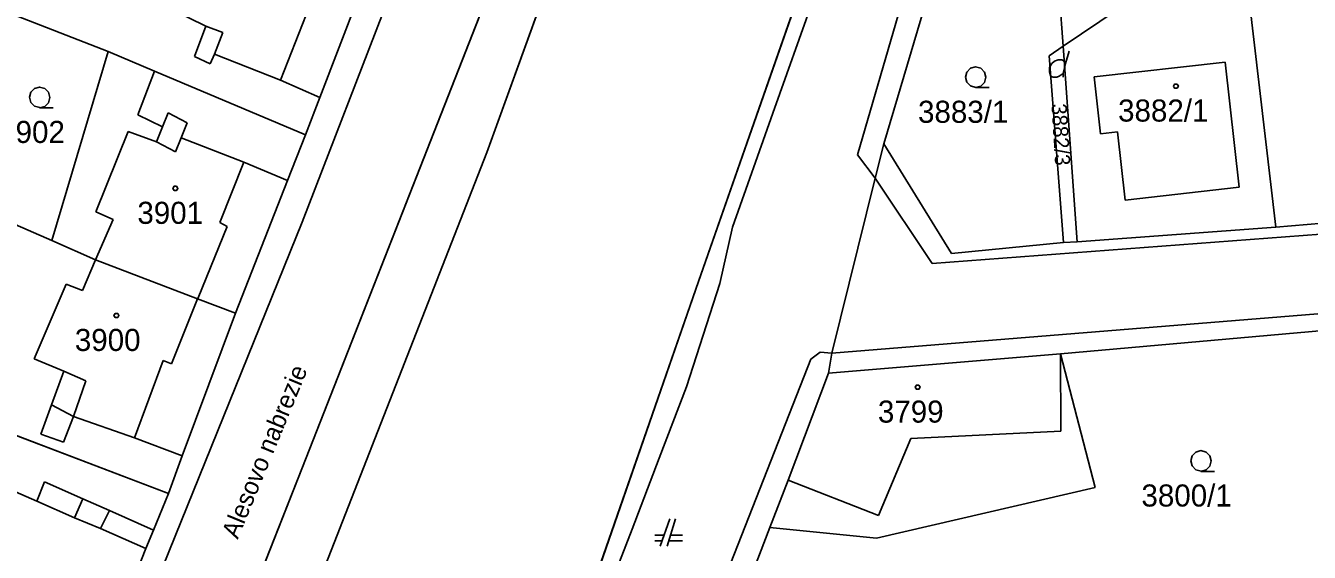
# Model space of a CAD drawing. Extents: x -263587 to -261993, y -1238795 to -1236748.
# Drawn here: x -262910.7 to -262817.7, y -1238176 to -1238137.9 of the extents above; entities that cross this region are included whole.
import ezdxf

# ---------------------------------------------------------------- set-up
doc = ezdxf.new("R2010")
doc.units = 0
for name, color, linetype in [('Vrstva 1', 7, 'Continuous'), ('Vrstva 2', 7, 'Continuous'), ('Vrstva 3', 7, 'Continuous')]:
    doc.layers.add(name, color=color, linetype=linetype)

msp = doc.modelspace()

# ---------------------------------------------------------------- linework, layer by layer
at = {"layer": 'Vrstva 1'}
for p, q in [((-262866.29, -1238107.87), (-262890.35, -1238169.19)), ((-262876.21, -1238114.77), (-262890.62, -1238152.1)), ((-262840.79, -1238114.19), (-262850.4, -1238147.22)), ((-262867.06, -1238118.93), (-262877.26, -1238147.05)), ((-262877.26, -1238147.05), (-262867.06, -1238118.93)), ((-262861.93, -1238156.4), (-262852.81, -1238130.33)), ((-262852.81, -1238130.33), (-262861.93, -1238156.4)), ((-262844.29, -1238132.25), (-262848.49, -1238146.42)), ((-262848.49, -1238146.42), (-262844.29, -1238132.25)), ((-262885.33, -1238132.63), (-262889.36, -1238143.08)), ((-262889.36, -1238143.08), (-262885.33, -1238132.63)), ((-262835.51, -1238139.35), (-262826.23, -1238133.08)), ((-262826.23, -1238133.08), (-262835.51, -1238139.35)), ((-262820.12, -1238152.47), (-262822.35, -1238133.41)), ((-262822.35, -1238133.41), (-262820.12, -1238152.47)), ((-262835.51, -1238139.35), (-262835.88, -1238134.17)), ((-262835.88, -1238134.17), (-262835.51, -1238139.35)), ((-262912.18, -1238136.81), (-262904.69, -1238139.75)), ((-262904.69, -1238139.75), (-262912.18, -1238136.81)), ((-262900.12, -1238136.67), (-262897.61, -1238137.9)), ((-262890.33, -1238137.09), (-262892.19, -1238141.83)), ((-262898.43, -1238140.1), (-262897.61, -1238137.9)), ((-262897.61, -1238137.9), (-262896.38, -1238138.37)), ((-262896.38, -1238138.37), (-262896.97, -1238139.94)), ((-262904.69, -1238139.75), (-262908.77, -1238153.43)), ((-262908.77, -1238153.43), (-262904.69, -1238139.75)), ((-262904.69, -1238139.75), (-262901.32, -1238141.17)), ((-262901.32, -1238141.17), (-262904.69, -1238139.75)), ((-262896.97, -1238139.94), (-262897.29, -1238140.63)), ((-262892.19, -1238141.83), (-262896.97, -1238139.94)), ((-262836.52, -1238140.05), (-262835.51, -1238139.35)), ((-262835.51, -1238139.35), (-262836.52, -1238140.05)), ((-262835.48, -1238153.58), (-262836.52, -1238140.05)), ((-262836.52, -1238140.05), (-262835.48, -1238153.58)), ((-262834.5, -1238153.53), (-262835.51, -1238139.35)), ((-262835.51, -1238139.35), (-262834.5, -1238153.53)), ((-262835.34, -1238140.62), (-262835.07, -1238139.72)), ((-262897.29, -1238140.63), (-262898.43, -1238140.1)), ((-262833.26, -1238141.57), (-262823.79, -1238140.51)), ((-262823.79, -1238140.51), (-262822.77, -1238149.58)), ((-262901.32, -1238141.17), (-262902.54, -1238144.34)), ((-262901.32, -1238141.17), (-262890.39, -1238145.77)), ((-262890.39, -1238145.77), (-262901.32, -1238141.17)), ((-262889.36, -1238143.08), (-262892.19, -1238141.83)), ((-262832.8, -1238145.7), (-262833.26, -1238141.57)), ((-262889.36, -1238143.08), (-262890.39, -1238145.77)), ((-262890.39, -1238145.77), (-262889.36, -1238143.08)), ((-262902.54, -1238144.34), (-262900.74, -1238145.2)), ((-262900.33, -1238144.19), (-262900.74, -1238145.2)), ((-262898.96, -1238144.9), (-262900.33, -1238144.19)), ((-262905.57, -1238151.35), (-262903.22, -1238145.53)), ((-262903.22, -1238145.53), (-262901.17, -1238146.29)), ((-262900.74, -1238145.2), (-262901.17, -1238146.29)), ((-262899.38, -1238146), (-262898.96, -1238144.9)), ((-262831.57, -1238145.57), (-262832.8, -1238145.7)), ((-262831.02, -1238150.51), (-262831.57, -1238145.57)), ((-262901.17, -1238146.29), (-262899.8, -1238147.02)), ((-262899.8, -1238147.02), (-262899.38, -1238146)), ((-262894.86, -1238147.75), (-262899.38, -1238146)), ((-262890.39, -1238145.77), (-262891.69, -1238149.1)), ((-262891.69, -1238149.1), (-262890.39, -1238145.77)), ((-262849.13, -1238148.92), (-262848.49, -1238146.42)), ((-262848.49, -1238146.42), (-262849.13, -1238148.92)), ((-262848.49, -1238146.42), (-262843.6, -1238154.37)), ((-262843.6, -1238154.37), (-262848.49, -1238146.42)), ((-262877.26, -1238147.05), (-262889.19, -1238177.55)), ((-262889.19, -1238177.55), (-262877.26, -1238147.05)), ((-262850.4, -1238147.22), (-262849.13, -1238148.92)), ((-262896.6, -1238152.13), (-262894.86, -1238147.75)), ((-262891.69, -1238149.1), (-262894.86, -1238147.75)), ((-262891.69, -1238149.1), (-262895.45, -1238158.69)), ((-262895.45, -1238158.69), (-262891.69, -1238149.1)), ((-262852.27, -1238161.6), (-262849.13, -1238148.92)), ((-262849.13, -1238148.92), (-262852.27, -1238161.6)), ((-262844.99, -1238155.11), (-262849.13, -1238148.92)), ((-262822.77, -1238149.58), (-262831.02, -1238150.51)), ((-262788.07, -1238150.8), (-262844.99, -1238155.11)), ((-262805.26, -1238151.2), (-262820.12, -1238152.47)), ((-262820.12, -1238152.47), (-262805.26, -1238151.2)), ((-262911.8, -1238152.11), (-262908.77, -1238153.43)), ((-262908.77, -1238153.43), (-262911.8, -1238152.11)), ((-262890.62, -1238152.1), (-262911.24, -1238203.07)), ((-262905.6, -1238154.83), (-262904.31, -1238151.92)), ((-262904.31, -1238151.92), (-262905.57, -1238151.35)), ((-262896.06, -1238152.41), (-262896.6, -1238152.13)), ((-262898.17, -1238157.59), (-262896.06, -1238152.41)), ((-262834.5, -1238153.53), (-262820.12, -1238152.47)), ((-262820.12, -1238152.47), (-262834.5, -1238153.53)), ((-262908.77, -1238153.43), (-262905.6, -1238154.83)), ((-262905.6, -1238154.83), (-262908.77, -1238153.43)), ((-262843.6, -1238154.37), (-262835.48, -1238153.58)), ((-262835.48, -1238153.58), (-262843.6, -1238154.37)), ((-262835.48, -1238153.58), (-262834.5, -1238153.53)), ((-262834.5, -1238153.53), (-262835.48, -1238153.58)), ((-262905.6, -1238154.83), (-262906.53, -1238157.05)), ((-262905.6, -1238154.83), (-262898.2, -1238157.65)), ((-262898.2, -1238157.65), (-262905.6, -1238154.83)), ((-262852.27, -1238161.6), (-262777.99, -1238155.57)), ((-262907.71, -1238156.59), (-262910.04, -1238162.01)), ((-262906.53, -1238157.05), (-262907.71, -1238156.59)), ((-262871.55, -1238184.14), (-262861.93, -1238156.4)), ((-262861.93, -1238156.4), (-262871.55, -1238184.14)), ((-262898.2, -1238157.65), (-262900.09, -1238162.36)), ((-262898.2, -1238157.65), (-262898.17, -1238157.59)), ((-262898.2, -1238157.65), (-262895.45, -1238158.69)), ((-262895.45, -1238158.69), (-262898.2, -1238157.65)), ((-262895.45, -1238158.69), (-262899.31, -1238169.04)), ((-262899.31, -1238169.04), (-262895.45, -1238158.69)), ((-262835.71, -1238161.65), (-262814.27, -1238159.75)), ((-262814.27, -1238159.75), (-262835.71, -1238161.65)), ((-262910.04, -1238162.01), (-262907.88, -1238162.9)), ((-262900.7, -1238162.13), (-262902.77, -1238167.73)), ((-262900.09, -1238162.36), (-262900.7, -1238162.13)), ((-262853.79, -1238162.03), (-262883.15, -1238236.73)), ((-262853.11, -1238161.52), (-262853.79, -1238162.03)), ((-262852.27, -1238161.6), (-262853.11, -1238161.52)), ((-262852.5, -1238163.05), (-262852.27, -1238161.6)), ((-262852.27, -1238161.6), (-262852.5, -1238163.05)), ((-262852.5, -1238163.05), (-262835.71, -1238161.65)), ((-262835.71, -1238161.65), (-262852.5, -1238163.05)), ((-262833.19, -1238171.34), (-262835.71, -1238161.65)), ((-262835.71, -1238161.65), (-262833.19, -1238171.34)), ((-262835.71, -1238161.65), (-262835.69, -1238167.25)), ((-262907.88, -1238162.9), (-262908.78, -1238165.35)), ((-262906.3, -1238163.61), (-262907.88, -1238162.9)), ((-262855.44, -1238170.79), (-262852.5, -1238163.05)), ((-262852.5, -1238163.05), (-262855.44, -1238170.79)), ((-262907.2, -1238166.18), (-262906.3, -1238163.61)), ((-262908.78, -1238165.35), (-262909.55, -1238167.46)), ((-262907.2, -1238166.18), (-262908.78, -1238165.35)), ((-262914.79, -1238166.26), (-262900.32, -1238171.76)), ((-262900.32, -1238171.76), (-262914.79, -1238166.26)), ((-262907.92, -1238168.05), (-262907.2, -1238166.18)), ((-262902.77, -1238167.73), (-262907.2, -1238166.18)), ((-262909.55, -1238167.46), (-262907.92, -1238168.05)), ((-262899.31, -1238169.04), (-262902.77, -1238167.73)), ((-262846.54, -1238167.79), (-262848.89, -1238173.37)), ((-262835.69, -1238167.25), (-262846.54, -1238167.79)), ((-262890.35, -1238169.19), (-262909.94, -1238218.9)), ((-262899.31, -1238169.04), (-262900.32, -1238171.76)), ((-262900.32, -1238171.76), (-262899.31, -1238169.04)), ((-262909.85, -1238172.32), (-262911.78, -1238171.47)), ((-262909.28, -1238170.92), (-262909.85, -1238172.32)), ((-262906.52, -1238172.14), (-262909.28, -1238170.92)), ((-262856.75, -1238174.24), (-262855.44, -1238170.79)), ((-262855.44, -1238170.79), (-262856.75, -1238174.24)), ((-262848.89, -1238173.37), (-262855.44, -1238170.79)), ((-262849.02, -1238175), (-262833.19, -1238171.34)), ((-262833.19, -1238171.34), (-262849.02, -1238175)), ((-262909.85, -1238172.32), (-262907.12, -1238173.52)), ((-262907.12, -1238173.52), (-262906.52, -1238172.14)), ((-262904.57, -1238173), (-262906.52, -1238172.14)), ((-262900.32, -1238171.76), (-262901.39, -1238174.41)), ((-262901.39, -1238174.41), (-262900.32, -1238171.76)), ((-262907.12, -1238173.52), (-262905.24, -1238174.31)), ((-262905.24, -1238174.31), (-262904.57, -1238173)), ((-262901.39, -1238174.41), (-262904.57, -1238173)), ((-262901.94, -1238175.75), (-262905.24, -1238174.31)), ((-262901.39, -1238174.41), (-262901.94, -1238175.75)), ((-262901.94, -1238175.75), (-262901.39, -1238174.41)), ((-262863.99, -1238173.59), (-262864.69, -1238175.59)), ((-262864.19, -1238175.59), (-262863.59, -1238173.59)), ((-262860.69, -1238184.41), (-262856.75, -1238174.24)), ((-262856.75, -1238174.24), (-262860.69, -1238184.41)), ((-262856.75, -1238174.24), (-262849.02, -1238175)), ((-262849.02, -1238175), (-262856.75, -1238174.24)), ((-262864.41, -1238174.79), (-262865.09, -1238174.79)), ((-262865.09, -1238175.19), (-262864.55, -1238175.19)), ((-262864.07, -1238175.19), (-262863.09, -1238175.19)), ((-262863.09, -1238174.79), (-262863.95, -1238174.79)), ((-262901.94, -1238175.75), (-262905.49, -1238184.52)), ((-262905.49, -1238184.52), (-262901.94, -1238175.75))]:
    msp.add_line(p, q, dxfattribs=at)
for points in [[(-262841.84, -1238142.34), (-262842.22, -1238142.24), (-262842.49, -1238141.97), (-262842.59, -1238141.6), (-262842.49, -1238141.23), (-262842.22, -1238140.96), (-262841.85, -1238140.86), (-262841.48, -1238140.96), (-262841.21, -1238141.23), (-262841.11, -1238141.61), (-262841.21, -1238141.99), (-262841.48, -1238142.26), (-262841.86, -1238142.36), (-262840.86, -1238142.36)], [(-262835.52, -1238141.61), (-262835.52, -1238141.34), (-262835.34, -1238140.62), (-262835.43, -1238140.44), (-262835.61, -1238140.35), (-262835.88, -1238140.35), (-262836.15, -1238140.44), (-262836.33, -1238140.62), (-262836.51, -1238140.89), (-262836.51, -1238141.25), (-262836.42, -1238141.52), (-262836.24, -1238141.61), (-262835.97, -1238141.61), (-262835.79, -1238141.52), (-262835.52, -1238141.34)], [(-262909.63, -1238143.8), (-262910.01, -1238143.7), (-262910.28, -1238143.43), (-262910.38, -1238143.06), (-262910.28, -1238142.69), (-262910.01, -1238142.42), (-262909.64, -1238142.32), (-262909.27, -1238142.42), (-262909, -1238142.69), (-262908.9, -1238143.07), (-262909, -1238143.45), (-262909.27, -1238143.72), (-262909.65, -1238143.82), (-262908.65, -1238143.82)], [(-262825.52, -1238170.14), (-262825.9, -1238170.04), (-262826.17, -1238169.77), (-262826.27, -1238169.4), (-262826.17, -1238169.03), (-262825.9, -1238168.76), (-262825.53, -1238168.66), (-262825.16, -1238168.76), (-262824.89, -1238169.03), (-262824.79, -1238169.41), (-262824.89, -1238169.79), (-262825.16, -1238170.06), (-262825.54, -1238170.16), (-262824.54, -1238170.16)]]:
    msp.add_lwpolyline(points, dxfattribs=at)
for points in [[(-262827.26, -1238142.1), (-262827.17, -1238142.25), (-262827.26, -1238142.4), (-262827.44, -1238142.4), (-262827.53, -1238142.25), (-262827.44, -1238142.1)], [(-262899.72, -1238149.51), (-262899.63, -1238149.66), (-262899.72, -1238149.81), (-262899.9, -1238149.81), (-262899.99, -1238149.66), (-262899.9, -1238149.51)], [(-262903.99, -1238158.72), (-262903.9, -1238158.87), (-262903.99, -1238159.02), (-262904.17, -1238159.02), (-262904.26, -1238158.87), (-262904.17, -1238158.72)], [(-262845.96, -1238163.91), (-262845.87, -1238164.06), (-262845.96, -1238164.21), (-262846.14, -1238164.21), (-262846.23, -1238164.06), (-262846.14, -1238163.91)]]:
    msp.add_lwpolyline(points, close=True, dxfattribs=at)
at = {"layer": 'Vrstva 2'}
for points in [[(-262841.835, -1237990.465), (-262844.48, -1238033.79), (-262845.25, -1238048.39), (-262849.38, -1238065.83), (-262857.835, -1238086.85), (-262866.29, -1238107.87), (-262866.29, -1238107.87), (-262878.32, -1238138.53), (-262890.35, -1238169.19), (-262900.145, -1238194.045), (-262912.404, -1238225.097), (-262915.95, -1238234.65), (-262915.99, -1238237.27), (-262914.68, -1238240.69), (-262912.88, -1238240.83), (-262912.88, -1238240.83), (-262914.78, -1238249.25)], [(-262874.069, -1238193.289), (-262866.716, -1238174.359), (-262864.76, -1238169.2), (-262862.798, -1238164.04), (-262861.594, -1238160.29), (-262860.39, -1238156.54), (-262859.461, -1238152.467), (-262856.535, -1238144.22), (-262853.61, -1238135.97), (-262850.709, -1238127.586), (-262847.806, -1238119.202), (-262845.541, -1238112.855), (-262843.275, -1238106.507), (-262841.484, -1238102.164), (-262840.587, -1238099.992), (-262836.47, -1238091.81), (-262833.139, -1238083.52), (-262832.135, -1238081.046), (-262829.415, -1238073.171)]]:
    msp.add_lwpolyline(points, dxfattribs=at)
at = {"layer": 'Vrstva 3'}
msp.add_lwpolyline([(-262898.67, -1238252.06), (-262915.44, -1238253.09), (-262914.91, -1238250.99), (-262914.78, -1238249.25), (-262912.88, -1238240.83), (-262912.46, -1238239.2), (-262911.89, -1238236.09), (-262899.67, -1238204.29), (-262889.19, -1238177.55), (-262877.26, -1238147.05), (-262867.06, -1238118.93), (-262856.48, -1238092.52), (-262836.93, -1238065.69), (-262828.451, -1238056.971), (-262829.17, -1238061.74), (-262830.66, -1238071.6), (-262836.47, -1238091.81), (-262846.02, -1238110.67), (-262852.81, -1238130.33), (-262861.93, -1238156.4), (-262871.55, -1238184.14), (-262874.73, -1238193.08), (-262883.27, -1238215.99), (-262892.66, -1238238.48)], close=True, dxfattribs=at)

# ---------------------------------------------------------------- texts
at = {"layer": 'Vrstva 1'}
for s, p in [('3883/1', (-262846.024, -1238144.91)), ('3882/1', (-262831.534, -1238144.82)), ('3902', (-262912.573, -1238146.37)), ('3901', (-262902.564, -1238152.23)), ('3900', (-262907.093, -1238161.44)), ('3799', (-262848.93, -1238166.63)), ('3800/1', (-262829.843, -1238172.71))]:
    msp.add_text(s, height=1.6, dxfattribs=at).set_placement(p)
for s, height, rotation, p in [('3882/3', 1.1, 273.58735, (-262836.365, -1238143.547)), ('Alesovo nabrezie', 1.3, 67.60902, (-262895.294, -1238175.127))]:
    msp.add_text(s, height=height, rotation=rotation, dxfattribs=at).set_placement(p)

doc.saveas('drawing.dxf')
